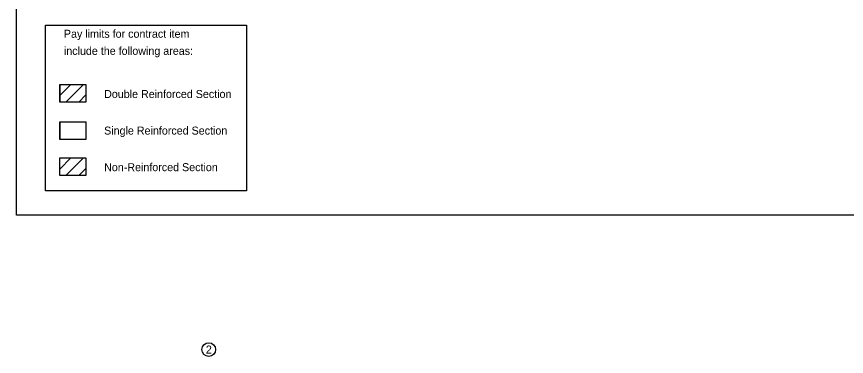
# Model space of a CAD drawing. Extents: x 10045 to 81668, y 6370 to 11018.
# Drawn here: x 20933 to 22837, y 7600 to 8380 of the extents above; entities that cross this region are included whole.
import ezdxf

# ---------------------------------------------------------------- set-up
doc = ezdxf.new("R2010")
doc.units = 0
for name, color, linetype in [('Alignment', 7, 'Continuous'), ('dsnStdLineWork', 7, 'Continuous'), ('Level 5', 7, 'Continuous')]:
    doc.layers.add(name, color=color, linetype=linetype)

msp = doc.modelspace()

# ---------------------------------------------------------------- linework, layer by layer
at = {"layer": 'Alignment'}
for p, q in [((21031.6, 8224.3), (21091.3, 8224.3)), ((21031.6, 8183.8), (21031.6, 8224.3)), ((21091.3, 8224.3), (21091.3, 8183.8)), ((21091.3, 8183.8), (21031.6, 8183.8)), ((21031.6, 8138.2), (21091.3, 8138.2)), ((21031.6, 8097.8), (21031.6, 8138.2)), ((21091.3, 8138.2), (21091.3, 8097.8)), ((21091.3, 8097.8), (21031.6, 8097.8))]:
    msp.add_line(p, q, dxfattribs=at)
at = {"layer": 'dsnStdLineWork'}
for p, q in [((21031.6, 8224.3), (21091.3, 8224.3)), ((21031.6, 8224.3), (21031.6, 8183.8)), ((21031.6, 8198.7), (21057.3, 8224.3)), ((21045.9, 8183.8), (21086.4, 8224.3)), ((21091.3, 8224.3), (21091.3, 8183.8)), ((21075, 8183.8), (21091.3, 8200.2)), ((21091.3, 8183.8), (21031.6, 8183.8)), ((21031.6, 8138.2), (21091.3, 8138.2)), ((21031.6, 8138.2), (21031.6, 8097.8)), ((21091.3, 8138.2), (21091.3, 8097.8)), ((21091.3, 8097.8), (21031.6, 8097.8)), ((21031.6, 8029.6), (21057.3, 8055.3)), ((21045.9, 8014.8), (21086.4, 8055.3)), ((21075, 8014.8), (21091.3, 8031.2))]:
    msp.add_line(p, q, dxfattribs=at)
for points in [[(20998.9, 8360.3), (21460.2, 8360.3), (21460.2, 7980), (20998.9, 7980)], [(21031.6, 8055.3), (21091.3, 8055.3), (21091.3, 8014.8), (21031.6, 8014.8)]]:
    msp.add_lwpolyline(points, close=True, dxfattribs=at)
msp.add_circle((21373.6, 7615.5), 15.7, dxfattribs=at)
at = {"layer": 'Level 5'}
msp.add_lwpolyline([(20932.5, 9944), (24067.5, 9944), (24067.5, 7924), (20932.5, 7924)], close=True, dxfattribs=at)

# ---------------------------------------------------------------- texts
at = {"layer": 'Alignment'}
for s, height, p in [('Pay limits for contract item', 18.375, (21041.1, 8331.3)), ('include the following areas:', 18.375, (21041.1, 8292)), ('Double Reinforced Section', 18.375, (21133.4, 8193)), ('Single Reinforced Section', 18.375, (21133.4, 8109)), ('Non-Reinforced Section', 18.375, (21133.4, 8025)), ('2', 18.4, (21367, 7606.3))]:
    msp.add_text(s, height=height, dxfattribs=at).set_placement(p)

doc.saveas('drawing.dxf')
